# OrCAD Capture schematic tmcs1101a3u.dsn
size A; title: TMCS1101 1.5% Precision, Basic Isolation Hall-Effect Current Sensor; rev: A; note: SBOS825
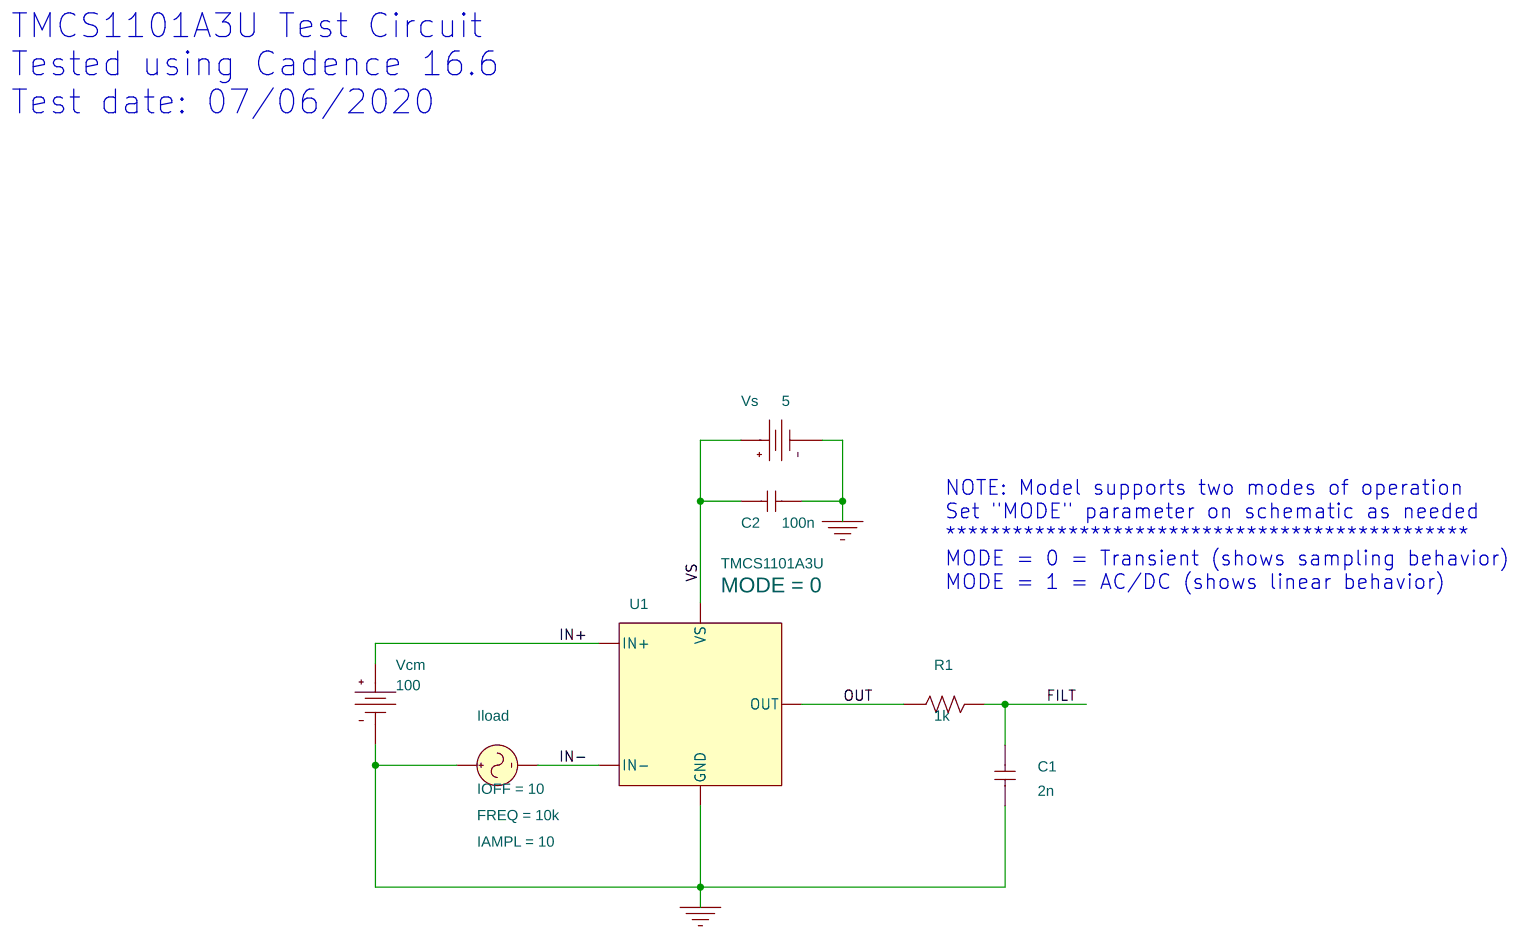
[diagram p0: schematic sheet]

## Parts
C1  2n  [RAD/CK05]
C2  100n  [RAD/CK05]
Iload  ISIN
R1  1k  [AX/RC05]
U1  TMCS1101A3U
Vcm  VDC
Vs  VDC

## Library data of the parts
C1 C2 = C
Iload = ISIN: FREQ: 10k; IAMPL: 10; IOFF: 10
R1 = R
U1 = TMCS1101A3U: MODE: 0
Vcm = VDC: DC: 100
Vs = VDC: DC: 5

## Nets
0: C1.1 C2.1 Iload.1(+) U1.GND Vcm.1(-) Vs.1(-)
FILT: C1.2 R1.2
IN+: U1.IN+ Vcm.0(+)
IN-: Iload.2(-) U1.IN-
OUT: R1.1 U1.OUT
VS: C2.2 U1.VS Vs.0(+)

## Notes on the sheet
- TMCS1101A3U Test Circuit
  Tested using Cadence 16.6
  Test date: 07/06/2020
- NOTE: Model supports two modes of operation
  Set "MODE" parameter on schematic as needed
  ***********************************************
  MODE = 0 = Transient (shows sampling behavior)
  MODE = 1 = AC/DC (shows linear behavior)
